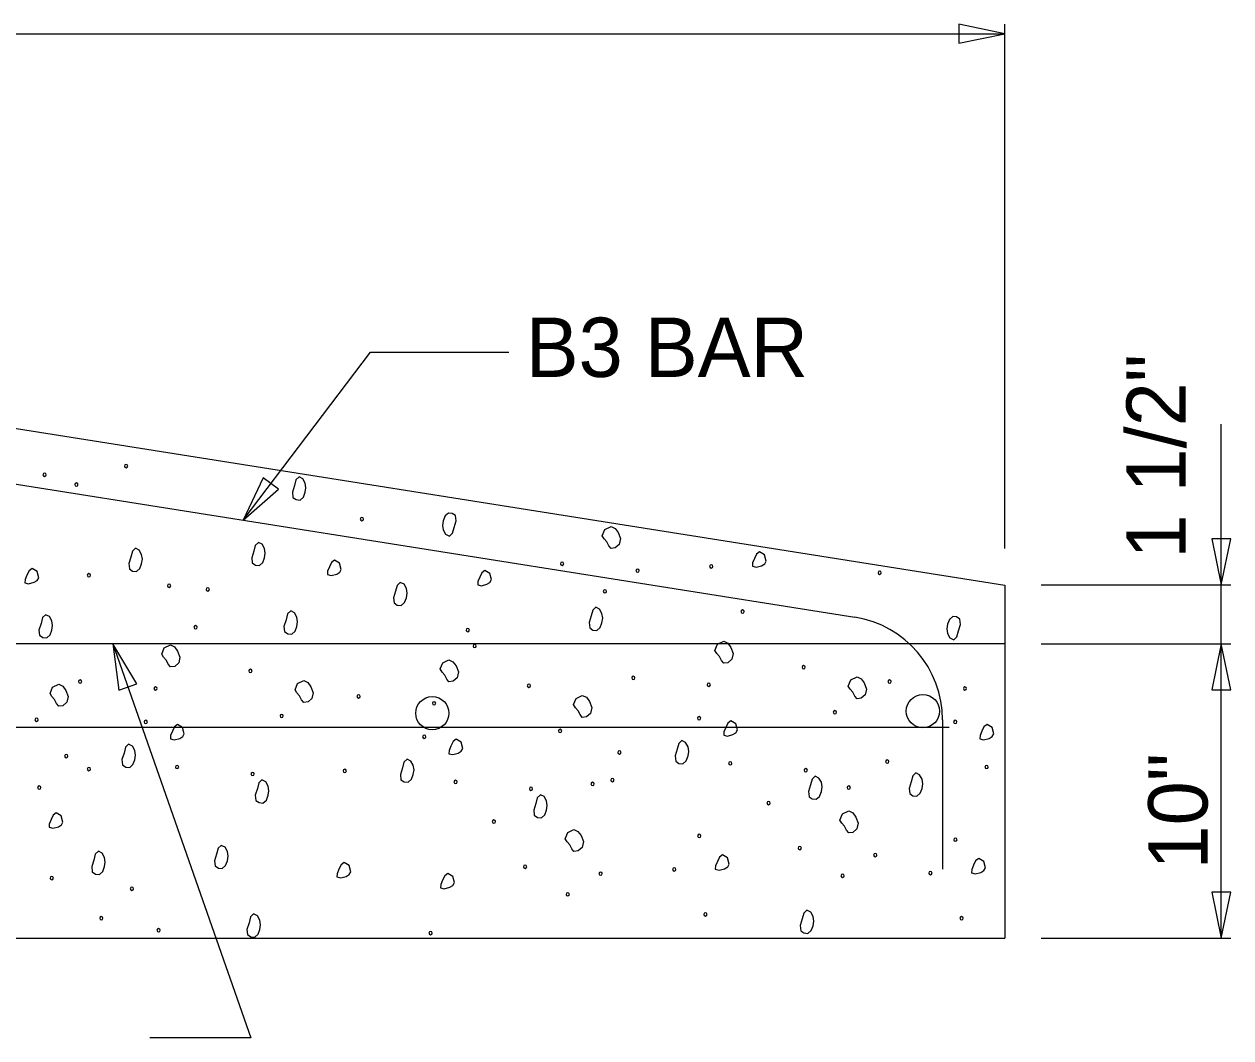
# Model space of a CAD drawing. Extents: x -439.2 to -407.9, y -458.1 to -436.2.
# Drawn here: x -419.02 to -415.969, y -450.772 to -448.209 of the extents above; entities that cross this region are included whole.
import ezdxf

# ---------------------------------------------------------------- set-up
doc = ezdxf.new("R2010")
doc.units = 0
doc.layers.add('Level 4', color=7, linetype='Continuous')
doc.layers.add('Level 45', color=7, linetype='Continuous')

msp = doc.modelspace()

# ---------------------------------------------------------------- linework, layer by layer
at = {"layer": 'Level 4'}
for p, q in [((-416.5408, -449.5349), (-416.5408, -448.2093)), ((-422.0412, -448.2334), (-416.5408, -448.2334)), ((-423.4518, -448.532), (-416.5407, -449.6272)), ((-421.5448, -448.9753), (-416.9196, -449.7086)), ((-418.4662, -449.4634), (-418.1444, -449.0382)), ((-418.1444, -449.0382), (-417.7942, -449.0382)), ((-415.9932, -450.5202), (-415.9932, -449.2206)), ((-416.5407, -449.6272), (-416.5407, -450.5197)), ((-416.4489, -449.6268), (-415.9691, -449.6268)), ((-423.4518, -449.7752), (-416.5407, -449.7752)), ((-418.7957, -449.7757), (-418.4463, -450.772)), ((-416.4489, -449.7757), (-415.9691, -449.7757)), ((-416.6982, -449.9679), (-416.6982, -450.3454)), ((-423.4518, -449.9863), (-416.6814, -449.9863)), ((-423.4518, -450.5197), (-416.5407, -450.5197)), ((-416.4489, -450.5202), (-415.9691, -450.5202)), ((-418.4463, -450.772), (-418.7015, -450.772))]:
    msp.add_line(p, q, dxfattribs=at)
for points in [[(-416.6569, -448.2575), (-416.5408, -448.2334), (-416.6569, -448.2093)], [(-418.4153, -449.3562), (-418.4662, -449.4634), (-418.3768, -449.3853)], [(-418.3246, -449.3539), (-418.3326, -449.3613), (-418.3363, -449.376), (-418.3416, -449.3927), (-418.3402, -449.4058), (-418.332, -449.4114), (-418.322, -449.4123), (-418.3136, -449.4049), (-418.309, -449.3928), (-418.3072, -449.3811), (-418.309, -449.3695), (-418.3151, -449.3586), (-418.3246, -449.3539)], [(-417.9446, -449.5036), (-417.9366, -449.4962), (-417.9329, -449.4816), (-417.9276, -449.4648), (-417.929, -449.4517), (-417.9372, -449.4461), (-417.9472, -449.4452), (-417.9556, -449.4526), (-417.9602, -449.4647), (-417.962, -449.4764), (-417.9602, -449.4881), (-417.9541, -449.4989), (-417.9446, -449.5036)], [(-417.5581, -449.5025), (-417.5515, -449.4868), (-417.536, -449.4792), (-417.5258, -449.484), (-417.5179, -449.4947), (-417.5122, -449.51), (-417.5153, -449.5246), (-417.5253, -449.5334), (-417.536, -449.535), (-417.5415, -449.5279), (-417.5464, -449.5181), (-417.5534, -449.5105), (-417.5581, -449.5025)], [(-418.4275, -449.5194), (-418.4354, -449.5269), (-418.4392, -449.5415), (-418.4444, -449.5583), (-418.443, -449.5713), (-418.4348, -449.5769), (-418.4249, -449.5778), (-418.4164, -449.5705), (-418.4119, -449.5584), (-418.4101, -449.5466), (-418.4119, -449.535), (-418.4179, -449.5242), (-418.4275, -449.5194)], [(-416.0173, -449.5106), (-415.9932, -449.6268), (-415.9691, -449.5106)], [(-418.7381, -449.5343), (-418.746, -449.5418), (-418.7497, -449.5564), (-418.7551, -449.5732), (-418.7536, -449.5863), (-418.7455, -449.5919), (-418.7355, -449.5927), (-418.727, -449.5854), (-418.7225, -449.5733), (-418.7207, -449.5615), (-418.7225, -449.5499), (-418.7285, -449.5391), (-418.7381, -449.5343)], [(-417.1604, -449.5433), (-417.1681, -449.5492), (-417.1733, -449.5602), (-417.1781, -449.5715), (-417.1785, -449.5797), (-417.1691, -449.582), (-417.1552, -449.5784), (-417.1474, -449.5736), (-417.1435, -449.5667), (-417.1477, -449.5508), (-417.1604, -449.5433)], [(-418.9996, -449.5854), (-419.0073, -449.5913), (-419.0125, -449.6022), (-419.0173, -449.6135), (-419.0177, -449.6217), (-419.0083, -449.624), (-418.9944, -449.6204), (-418.9866, -449.6157), (-418.9827, -449.6087), (-418.9869, -449.5928), (-418.9996, -449.5854)], [(-418.2347, -449.5643), (-418.2424, -449.5702), (-418.2476, -449.5812), (-418.2524, -449.5924), (-418.2528, -449.6007), (-418.2433, -449.603), (-418.2295, -449.5994), (-418.2217, -449.5946), (-418.2178, -449.5877), (-418.222, -449.5717), (-418.2347, -449.5643)], [(-417.8549, -449.5903), (-417.8627, -449.5962), (-417.8679, -449.6071), (-417.8727, -449.6184), (-417.8731, -449.6266), (-417.8636, -449.629), (-417.8497, -449.6253), (-417.842, -449.6206), (-417.8381, -449.6136), (-417.8423, -449.5977), (-417.8549, -449.5903)], [(-418.0689, -449.6206), (-418.0768, -449.628), (-418.0806, -449.6427), (-418.0859, -449.6594), (-418.0845, -449.6725), (-418.0763, -449.6781), (-418.0663, -449.679), (-418.0579, -449.6716), (-418.0533, -449.6595), (-418.0515, -449.6478), (-418.0533, -449.6362), (-418.0593, -449.6253), (-418.0689, -449.6206)], [(-418.9652, -449.7022), (-418.9731, -449.7097), (-418.9769, -449.7243), (-418.9821, -449.7411), (-418.9807, -449.7541), (-418.9726, -449.7597), (-418.9626, -449.7606), (-418.9541, -449.7533), (-418.9496, -449.7412), (-418.9478, -449.7294), (-418.9496, -449.7178), (-418.9556, -449.707), (-418.9652, -449.7022)], [(-418.3457, -449.6928), (-418.3536, -449.7003), (-418.3574, -449.7149), (-418.3627, -449.7317), (-418.3613, -449.7448), (-418.3531, -449.7504), (-418.3431, -449.7513), (-418.3347, -449.7439), (-418.3301, -449.7318), (-418.3283, -449.7201), (-418.3301, -449.7084), (-418.3361, -449.6976), (-418.3457, -449.6928)], [(-417.5744, -449.6835), (-417.5823, -449.6909), (-417.5861, -449.7055), (-417.5913, -449.7223), (-417.5899, -449.7354), (-417.5817, -449.741), (-417.5718, -449.7419), (-417.5633, -449.7345), (-417.5588, -449.7224), (-417.557, -449.7107), (-417.5588, -449.699), (-417.5648, -449.6882), (-417.5744, -449.6835)], [(-416.6697, -449.7655), (-416.6617, -449.758), (-416.658, -449.7434), (-416.6527, -449.7266), (-416.6541, -449.7135), (-416.6623, -449.7079), (-416.6723, -449.707), (-416.6807, -449.7144), (-416.6852, -449.7265), (-416.6871, -449.7382), (-416.6852, -449.7499), (-416.6792, -449.7607), (-416.6697, -449.7655)], [(-417.2732, -449.7926), (-417.2667, -449.7769), (-417.2512, -449.7692), (-417.2409, -449.7741), (-417.233, -449.7848), (-417.2273, -449.8001), (-417.2304, -449.8147), (-417.2405, -449.8235), (-417.2512, -449.825), (-417.2566, -449.818), (-417.2616, -449.8082), (-417.2686, -449.8006), (-417.2732, -449.7926)], [(-418.7345, -449.8773), (-418.7957, -449.7757), (-418.78, -449.8933)], [(-418.6718, -449.802), (-418.6652, -449.7862), (-418.6497, -449.7786), (-418.6394, -449.7835), (-418.6315, -449.7942), (-418.6258, -449.8095), (-418.6289, -449.824), (-418.639, -449.8329), (-418.6497, -449.8344), (-418.6552, -449.8274), (-418.6601, -449.8176), (-418.6671, -449.81), (-418.6718, -449.802)], [(-415.9691, -449.8918), (-415.9932, -449.7757), (-416.0173, -449.8918)], [(-417.9678, -449.8395), (-417.9613, -449.8238), (-417.9458, -449.8162), (-417.9355, -449.821), (-417.9276, -449.8317), (-417.9219, -449.847), (-417.925, -449.8616), (-417.935, -449.8704), (-417.9458, -449.872), (-417.9512, -449.8649), (-417.9561, -449.8551), (-417.9632, -449.8475), (-417.9678, -449.8395)], [(-416.9362, -449.8826), (-416.9296, -449.8669), (-416.9141, -449.8592), (-416.9038, -449.8641), (-416.896, -449.8748), (-416.8903, -449.8901), (-416.8934, -449.9047), (-416.9034, -449.9135), (-416.9141, -449.9151), (-416.9196, -449.908), (-416.9245, -449.8982), (-416.9315, -449.8906), (-416.9362, -449.8826)], [(-418.9542, -449.9014), (-418.9477, -449.8856), (-418.9322, -449.878), (-418.9219, -449.8829), (-418.914, -449.8936), (-418.9083, -449.9088), (-418.9114, -449.9234), (-418.9214, -449.9323), (-418.9322, -449.9338), (-418.9376, -449.9268), (-418.9425, -449.917), (-418.9496, -449.9094), (-418.9542, -449.9014)], [(-418.3347, -449.892), (-418.3282, -449.8763), (-418.3127, -449.8686), (-418.3024, -449.8735), (-418.2945, -449.8842), (-418.2888, -449.8995), (-418.2919, -449.9141), (-418.302, -449.9229), (-418.3127, -449.9244), (-418.3181, -449.9174), (-418.3231, -449.9076), (-418.3301, -449.9), (-418.3347, -449.892)], [(-417.6308, -449.9295), (-417.6242, -449.9138), (-417.6087, -449.9062), (-417.5984, -449.911), (-417.5905, -449.9217), (-417.5848, -449.937), (-417.588, -449.9516), (-417.598, -449.9604), (-417.6087, -449.962), (-417.6142, -449.9549), (-417.6191, -449.9451), (-417.6261, -449.9375), (-417.6308, -449.9295)], [(-418.6316, -449.9797), (-418.6394, -449.9856), (-418.6445, -449.9966), (-418.6493, -450.0078), (-418.6497, -450.0161), (-418.6403, -450.0184), (-418.6264, -450.0148), (-418.6186, -450.01), (-418.6147, -450.0031), (-418.6189, -449.9872), (-418.6316, -449.9797)], [(-417.233, -449.9704), (-417.2408, -449.9763), (-417.246, -449.9872), (-417.2508, -449.9985), (-417.2512, -450.0067), (-417.2417, -450.009), (-417.2278, -450.0054), (-417.2201, -450.0006), (-417.2162, -449.9937), (-417.2204, -449.9778), (-417.233, -449.9704)], [(-416.5854, -449.9797), (-416.5932, -449.9856), (-416.5984, -449.9966), (-416.6031, -450.0078), (-416.6036, -450.0161), (-416.5941, -450.0184), (-416.5802, -450.0148), (-416.5724, -450.01), (-416.5685, -450.0031), (-416.5728, -449.9872), (-416.5854, -449.9797)], [(-418.7554, -450.0298), (-418.7633, -450.0373), (-418.7671, -450.0519), (-418.7724, -450.0687), (-418.771, -450.0818), (-418.7628, -450.0874), (-418.7528, -450.0883), (-418.7444, -450.0809), (-418.7398, -450.0688), (-418.738, -450.0571), (-418.7398, -450.0454), (-418.7458, -450.0346), (-418.7554, -450.0298)], [(-417.9276, -450.0173), (-417.9354, -450.0232), (-417.9406, -450.0342), (-417.9453, -450.0454), (-417.9458, -450.0536), (-417.9363, -450.056), (-417.9224, -450.0523), (-417.9146, -450.0476), (-417.9107, -450.0407), (-417.915, -450.0247), (-417.9276, -450.0173)], [(-417.3569, -450.0205), (-417.3648, -450.0279), (-417.3685, -450.0425), (-417.3738, -450.0593), (-417.3724, -450.0724), (-417.3642, -450.078), (-417.3543, -450.0789), (-417.3458, -450.0715), (-417.3413, -450.0594), (-417.3395, -450.0477), (-417.3413, -450.036), (-417.3473, -450.0252), (-417.3569, -450.0205)], [(-418.0514, -450.0674), (-418.0594, -450.0748), (-418.0631, -450.0895), (-418.0684, -450.1062), (-418.067, -450.1193), (-418.0588, -450.1249), (-418.0488, -450.1258), (-418.0404, -450.1184), (-418.0359, -450.1063), (-418.034, -450.0946), (-418.0359, -450.083), (-418.0419, -450.0722), (-418.0514, -450.0674)], [(-416.7653, -450.1023), (-416.7733, -450.1097), (-416.777, -450.1244), (-416.7823, -450.1412), (-416.7809, -450.1542), (-416.7727, -450.1598), (-416.7627, -450.1607), (-416.7543, -450.1534), (-416.7497, -450.1413), (-416.7479, -450.1295), (-416.7497, -450.1179), (-416.7558, -450.1071), (-416.7653, -450.1023)], [(-418.4184, -450.1199), (-418.4263, -450.1273), (-418.43, -450.1419), (-418.4353, -450.1587), (-418.4339, -450.1718), (-418.4257, -450.1774), (-418.4158, -450.1783), (-418.4073, -450.1709), (-418.4028, -450.1588), (-418.4009, -450.1471), (-418.4028, -450.1354), (-418.4088, -450.1246), (-418.4184, -450.1199)], [(-417.0198, -450.1105), (-417.0277, -450.1179), (-417.0315, -450.1325), (-417.0368, -450.1493), (-417.0354, -450.1624), (-417.0272, -450.168), (-417.0172, -450.1689), (-417.0088, -450.1615), (-417.0042, -450.1494), (-417.0024, -450.1377), (-417.0042, -450.126), (-417.0103, -450.1152), (-417.0198, -450.1105)], [(-417.7144, -450.1574), (-417.7223, -450.1648), (-417.7261, -450.1795), (-417.7314, -450.1962), (-417.73, -450.2093), (-417.7218, -450.2149), (-417.7118, -450.2158), (-417.7034, -450.2084), (-417.6988, -450.1963), (-417.697, -450.1846), (-417.6988, -450.173), (-417.7048, -450.1622), (-417.7144, -450.1574)], [(-418.9383, -450.2034), (-418.9461, -450.2093), (-418.9513, -450.2202), (-418.9561, -450.2315), (-418.9565, -450.2397), (-418.947, -450.242), (-418.9331, -450.2384), (-418.9254, -450.2337), (-418.9215, -450.2267), (-418.9257, -450.2108), (-418.9383, -450.2034)], [(-416.9573, -450.2216), (-416.9507, -450.2058), (-416.9352, -450.1982), (-416.9249, -450.203), (-416.917, -450.2138), (-416.9113, -450.229), (-416.9144, -450.2436), (-416.9245, -450.2525), (-416.9352, -450.254), (-416.9407, -450.2469), (-416.9456, -450.2371), (-416.9526, -450.2296), (-416.9573, -450.2216)], [(-417.6518, -450.2685), (-417.6453, -450.2528), (-417.6298, -450.2451), (-417.6195, -450.25), (-417.6116, -450.2607), (-417.6059, -450.276), (-417.609, -450.2906), (-417.6191, -450.2994), (-417.6298, -450.3009), (-417.6352, -450.2939), (-417.6402, -450.2841), (-417.6472, -450.2765), (-417.6518, -450.2685)], [(-418.5212, -450.2854), (-418.5291, -450.2928), (-418.5329, -450.3075), (-418.5382, -450.3242), (-418.5368, -450.3373), (-418.5286, -450.3429), (-418.5186, -450.3438), (-418.5102, -450.3364), (-418.5056, -450.3243), (-418.5038, -450.3126), (-418.5056, -450.301), (-418.5116, -450.2901), (-418.5212, -450.2854)], [(-418.8318, -450.3003), (-418.8397, -450.3077), (-418.8435, -450.3224), (-418.8488, -450.3391), (-418.8474, -450.3522), (-418.8392, -450.3578), (-418.8292, -450.3587), (-418.8208, -450.3513), (-418.8162, -450.3392), (-418.8144, -450.3275), (-418.8162, -450.3159), (-418.8222, -450.3051), (-418.8318, -450.3003)], [(-417.2541, -450.3093), (-417.2619, -450.3152), (-417.2671, -450.3262), (-417.2718, -450.3374), (-417.2723, -450.3457), (-417.2628, -450.348), (-417.2489, -450.3444), (-417.2411, -450.3396), (-417.2372, -450.3327), (-417.2415, -450.3167), (-417.2541, -450.3093)], [(-416.6064, -450.3187), (-416.6142, -450.3246), (-416.6194, -450.3356), (-416.6242, -450.3468), (-416.6246, -450.355), (-416.6151, -450.3574), (-416.6012, -450.3538), (-416.5935, -450.349), (-416.5896, -450.3421), (-416.5938, -450.3261), (-416.6064, -450.3187)], [(-418.2107, -450.3289), (-418.2185, -450.3348), (-418.2237, -450.3458), (-418.2285, -450.357), (-418.2289, -450.3653), (-418.2194, -450.3676), (-418.2055, -450.364), (-418.1977, -450.3592), (-418.1938, -450.3523), (-418.1981, -450.3363), (-418.2107, -450.3289)], [(-417.9487, -450.3562), (-417.9564, -450.3621), (-417.9616, -450.3731), (-417.9664, -450.3844), (-417.9668, -450.3926), (-417.9574, -450.3949), (-417.9435, -450.3913), (-417.9357, -450.3865), (-417.9318, -450.3796), (-417.936, -450.3637), (-417.9487, -450.3562)], [(-416.0173, -450.404), (-415.9932, -450.5202), (-415.9691, -450.404)], [(-418.4394, -450.4588), (-418.4473, -450.4663), (-418.4511, -450.4809), (-418.4564, -450.4977), (-418.455, -450.5107), (-418.4468, -450.5163), (-418.4368, -450.5172), (-418.4284, -450.5098), (-418.4238, -450.4978), (-418.422, -450.486), (-418.4238, -450.4744), (-418.4299, -450.4636), (-418.4394, -450.4588)], [(-417.0409, -450.4494), (-417.0488, -450.4569), (-417.0526, -450.4715), (-417.0579, -450.4883), (-417.0565, -450.5013), (-417.0483, -450.5069), (-417.0383, -450.5078), (-417.0298, -450.5005), (-417.0253, -450.4884), (-417.0235, -450.4766), (-417.0253, -450.465), (-417.0313, -450.4542), (-417.0409, -450.4494)]]:
    msp.add_lwpolyline(points, close=True, dxfattribs=at)
for centre in [(-417.9878, -449.9511), (-416.7475, -449.9461)]:
    msp.add_circle(centre, 0.042, dxfattribs=at)
for centre, radius, start, end in [((-418.762, -449.3264), 0.00416, 0, 180), ((-418.762, -449.3264), 0.00416, 180, 0), ((-418.968, -449.3483), 0.00416, 0, 180), ((-418.968, -449.3483), 0.00416, 180, 0), ((-418.8875, -449.3734), 0.00416, 0, 180), ((-418.8875, -449.3734), 0.00416, 180, 0), ((-418.1657, -449.4607), 0.00416, 0, 180), ((-418.1657, -449.4607), 0.00416, 180, 0), ((-417.6596, -449.5734), 0.00416, 0, 180), ((-417.6596, -449.5734), 0.00416, 180, 0), ((-417.4688, -449.5909), 0.00416, 0, 180), ((-417.2826, -449.5802), 0.00416, 0, 180), ((-417.2826, -449.5802), 0.00416, 180, 0), ((-418.8559, -449.6023), 0.00416, 0, 180), ((-418.8559, -449.6023), 0.00416, 180, 0), ((-417.4688, -449.5909), 0.00416, 180, 0), ((-416.8569, -449.5963), 0.00416, 0, 180), ((-416.8569, -449.5963), 0.00416, 180, 0), ((-418.6533, -449.629), 0.00416, 0, 180), ((-418.6533, -449.629), 0.00416, 180, 0), ((-418.5554, -449.6383), 0.00416, 0, 180), ((-418.5554, -449.6383), 0.00416, 180, 0), ((-417.5514, -449.6432), 0.00416, 0, 180), ((-417.5514, -449.6432), 0.00416, 180, 0), ((-417.2036, -449.6942), 0.00416, 0, 180), ((-417.2036, -449.6942), 0.00416, 180, 0), ((-416.9607, -449.9678), 0.2625, 0, 80.9914), ((-418.5862, -449.7338), 0.00416, 0, 180), ((-418.5862, -449.7338), 0.00416, 180, 0), ((-417.8982, -449.7411), 0.00416, 0, 180), ((-417.8982, -449.7411), 0.00416, 180, 0), ((-417.8807, -449.7814), 0.00416, 0, 180), ((-417.8807, -449.7814), 0.00416, 180, 0), ((-417.049, -449.8349), 0.00416, 0, 180), ((-418.4475, -449.8443), 0.00416, 0, 180), ((-418.4475, -449.8443), 0.00416, 180, 0), ((-417.4796, -449.8619), 0.00416, 0, 180), ((-417.4796, -449.8619), 0.00416, 180, 0), ((-417.049, -449.8349), 0.00416, 180, 0), ((-418.8781, -449.8713), 0.00416, 0, 180), ((-418.8781, -449.8713), 0.00416, 180, 0), ((-418.6874, -449.8888), 0.00416, 0, 180), ((-418.6874, -449.8888), 0.00416, 180, 0), ((-417.7435, -449.8819), 0.00416, 0, 180), ((-417.7435, -449.8819), 0.00416, 180, 0), ((-417.2888, -449.8794), 0.00416, 0, 180), ((-417.2888, -449.8794), 0.00416, 180, 0), ((-416.832, -449.8713), 0.00416, 0, 180), ((-416.832, -449.8713), 0.00416, 180, 0), ((-416.6412, -449.8888), 0.00416, 0, 180), ((-416.6412, -449.8888), 0.00416, 180, 0), ((-418.1742, -449.9088), 0.00416, 0, 180), ((-418.1742, -449.9088), 0.00416, 180, 0), ((-417.9834, -449.9263), 0.00416, 0, 180), ((-417.9834, -449.9263), 0.00416, 180, 0), ((-416.97, -449.949), 0.00416, 0, 180), ((-416.97, -449.949), 0.00416, 180, 0), ((-418.988, -449.9677), 0.00416, 0, 180), ((-418.988, -449.9677), 0.00416, 180, 0), ((-418.712, -449.9733), 0.00416, 0, 180), ((-418.712, -449.9733), 0.00416, 180, 0), ((-418.3686, -449.9583), 0.00416, 0, 180), ((-418.3686, -449.9583), 0.00416, 180, 0), ((-417.3134, -449.9639), 0.00416, 0, 180), ((-417.3134, -449.9639), 0.00416, 180, 0), ((-416.6658, -449.9733), 0.00416, 0, 180), ((-416.6658, -449.9733), 0.00416, 180, 0), ((-418.008, -450.0109), 0.00416, 0, 180), ((-418.008, -450.0109), 0.00416, 180, 0), ((-417.6646, -449.9959), 0.00416, 0, 180), ((-417.6646, -449.9959), 0.00416, 180, 0), ((-418.9131, -450.0597), 0.00416, 0, 180), ((-418.9131, -450.0597), 0.00416, 180, 0), ((-417.5146, -450.0503), 0.00416, 0, 180), ((-417.5146, -450.0503), 0.00416, 180, 0), ((-417.2345, -450.078), 0.00416, 0, 180), ((-416.8377, -450.0736), 0.00416, 0, 180), ((-416.8377, -450.0736), 0.00416, 180, 0), ((-418.8557, -450.0924), 0.00416, 0, 180), ((-418.8557, -450.0924), 0.00416, 180, 0), ((-418.633, -450.0873), 0.00416, 0, 180), ((-418.633, -450.0873), 0.00416, 180, 0), ((-418.4422, -450.1049), 0.00416, 0, 180), ((-418.4422, -450.1049), 0.00416, 180, 0), ((-418.2092, -450.0973), 0.00416, 0, 180), ((-418.2092, -450.0973), 0.00416, 180, 0), ((-417.2345, -450.078), 0.00416, 180, 0), ((-417.0437, -450.0955), 0.00416, 0, 180), ((-417.0437, -450.0955), 0.00416, 180, 0), ((-416.5868, -450.0873), 0.00416, 0, 180), ((-416.5868, -450.0873), 0.00416, 180, 0), ((-418.9813, -450.1394), 0.00416, 0, 180), ((-417.9291, -450.1249), 0.00416, 0, 180), ((-417.9291, -450.1249), 0.00416, 180, 0), ((-417.5827, -450.13), 0.00416, 0, 180), ((-417.5827, -450.13), 0.00416, 180, 0), ((-417.5323, -450.1205), 0.00416, 0, 180), ((-417.5323, -450.1205), 0.00416, 180, 0), ((-416.9351, -450.1394), 0.00416, 0, 180), ((-418.9813, -450.1394), 0.00416, 180, 0), ((-417.7383, -450.1424), 0.00416, 0, 180), ((-417.7383, -450.1424), 0.00416, 180, 0), ((-416.9351, -450.1394), 0.00416, 180, 0), ((-417.1377, -450.1784), 0.00416, 0, 180), ((-417.1377, -450.1784), 0.00416, 180, 0), ((-417.8322, -450.2253), 0.00416, 0, 180), ((-417.8322, -450.2253), 0.00416, 180, 0), ((-417.313, -450.2616), 0.00416, 0, 180), ((-417.313, -450.2616), 0.00416, 180, 0), ((-417.0587, -450.2924), 0.00416, 0, 180), ((-416.6654, -450.271), 0.00416, 0, 180), ((-416.6654, -450.271), 0.00416, 180, 0), ((-417.0587, -450.2924), 0.00416, 180, 0), ((-416.8679, -450.31), 0.00416, 0, 180), ((-416.8679, -450.31), 0.00416, 180, 0), ((-417.7533, -450.3394), 0.00416, 0, 180), ((-417.7533, -450.3394), 0.00416, 180, 0), ((-417.3763, -450.3461), 0.00416, 0, 180), ((-417.3763, -450.3461), 0.00416, 180, 0), ((-418.9496, -450.3682), 0.00416, 0, 180), ((-418.9496, -450.3682), 0.00416, 180, 0), ((-417.5625, -450.3569), 0.00416, 0, 180), ((-417.5625, -450.3569), 0.00416, 180, 0), ((-416.9506, -450.3622), 0.00416, 0, 180), ((-416.9506, -450.3622), 0.00416, 180, 0), ((-416.7287, -450.3555), 0.00416, 0, 180), ((-416.7287, -450.3555), 0.00416, 180, 0), ((-418.7471, -450.395), 0.00416, 0, 180), ((-418.7471, -450.395), 0.00416, 180, 0), ((-417.6452, -450.4092), 0.00416, 0, 180), ((-417.6452, -450.4092), 0.00416, 180, 0), ((-418.8245, -450.4695), 0.00416, 0, 180), ((-418.8245, -450.4695), 0.00416, 180, 0), ((-417.2974, -450.4601), 0.00416, 0, 180), ((-417.2974, -450.4601), 0.00416, 180, 0), ((-416.6497, -450.4695), 0.00416, 0, 180), ((-416.6497, -450.4695), 0.00416, 180, 0), ((-418.6799, -450.4998), 0.00416, 0, 180), ((-418.6799, -450.4998), 0.00416, 180, 0), ((-417.992, -450.5071), 0.00416, 0, 180), ((-417.992, -450.5071), 0.00416, 180, 0)]:
    msp.add_arc(centre, radius, start, end, dxfattribs=at)

# ---------------------------------------------------------------- texts
msp.add_text('B3 BAR', height=0.15, dxfattribs=at).set_placement((-417.7517, -449.1012))
at = {"layer": 'Level 45'}
for s, p in [('1 1/2"', (-416.0831, -449.5606)), ('10"', (-416.028, -450.3463))]:
    msp.add_text(s, height=0.15, rotation=90, dxfattribs=at).set_placement(p)

doc.saveas('drawing.dxf')
